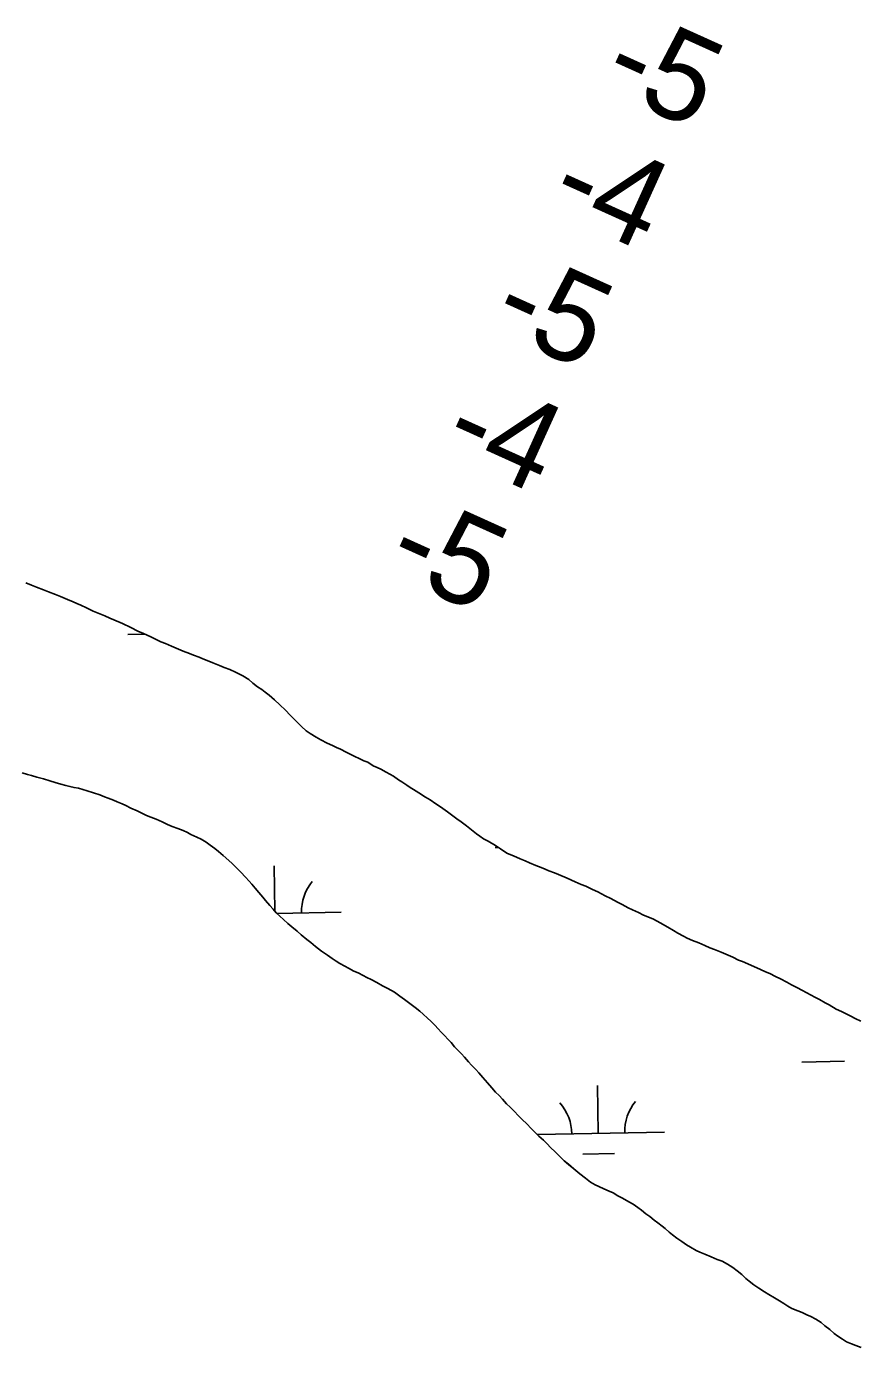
# Model space of a CAD drawing. Extents: x 3989314 to 4027622, y 243956 to 270014.
# Drawn here: x 4017755 to 4018382, y 254007 to 255004 of the extents above; entities that cross this region are included whole.
import ezdxf

# ---------------------------------------------------------------- set-up
doc = ezdxf.new("R2010")
doc.units = 0
for name, color, linetype in [('V-RIVR-EDGE', 7, 'Continuous'), ('V-RIVR-RANG', 7, 'Continuous'), ('V-WETL-SWMP', 7, 'Continuous')]:
    doc.layers.add(name, color=color, linetype=linetype)

msp = doc.modelspace()

# ---------------------------------------------------------------- linework, layer by layer
at = {"layer": 'V-RIVR-EDGE'}
for points in [[(4017754.1, 254584.42), (4017758.41, 254582.49), (4017762.19, 254580.94), (4017767.4, 254579.01), (4017771.32, 254577.47), (4017776.53, 254575.54), (4017780.45, 254574.13), (4017785.66, 254571.68), (4017789.84, 254569.87), (4017792.7, 254568.71), (4017795.71, 254567.56), (4017799.88, 254565.49), (4017805.1, 254563.04), (4017808.88, 254561.5), (4017813.83, 254559.31), (4017817.62, 254557.77), (4017820.49, 254556.48), (4017827.01, 254553.52), (4017833.4, 254550.55), (4017838.75, 254547.97), (4017842.93, 254546.04), (4017848.41, 254543.46), (4017852.97, 254541.27), (4017856.1, 254539.85), (4017859.49, 254538.43), (4017864.06, 254536.63), (4017869.27, 254534.31), (4017872.93, 254532.77), (4017877.62, 254531.1), (4017880.75, 254529.81), (4017884.92, 254528.27), (4017887.79, 254526.98), (4017892.1, 254525.31), (4017895.23, 254523.89), (4017900.18, 254521.83), (4017903.7, 254520.54), (4017908.01, 254518.87), (4017912.44, 254516.81), (4017917.79, 254514.23), (4017922.49, 254511.26), (4017925.5, 254508.54), (4017929.02, 254505.82), (4017932.16, 254503.75), (4017934.64, 254501.94)], [(4017934.64, 254501.94), (4017937.77, 254499.48), (4017941.69, 254496.12), (4017945.88, 254492.36), (4017950.06, 254488.21), (4017953.59, 254484.58), (4017956.08, 254481.99), (4017959.61, 254478.49), (4017962.09, 254475.9), (4017965.75, 254472.67), (4017968.76, 254470.6), (4017973.2, 254467.75), (4017976.59, 254465.95), (4017981.55, 254463.37), (4017985.46, 254461.56), (4017988.46, 254460.14), (4017991.46, 254458.73), (4017995.77, 254456.53), (4017998.77, 254454.98), (4018001.77, 254453.57), (4018006.21, 254451.5), (4018009.08, 254450.08), (4018012.08, 254448.93), (4018016.12, 254446.34), (4018019.12, 254445.05), (4018021.86, 254443.64), (4018025.91, 254441.44), (4018028.78, 254439.89), (4018031.39, 254438.34), (4018035.18, 254435.76), (4018037.79, 254434.08), (4018041.57, 254431.62), (4018044.06, 254429.81), (4018046.67, 254428.26), (4018050.58, 254425.93), (4018055.67, 254422.71), (4018059.07, 254420.51), (4018063.38, 254417.66), (4018066.9, 254415.34), (4018072.12, 254411.58), (4018076.17, 254408.61), (4018079.31, 254406.28), (4018082.45, 254403.95), (4018086.49, 254400.98), (4018088.98, 254398.9), (4018094.07, 254395.02), (4018096.55, 254393.08), (4018099.3, 254391.14), (4018102.95, 254389.34), (4018108.43, 254386.11), (4018112.22, 254383.52), (4018114.83, 254381.84), (4018117.57, 254380.16), (4018122.14, 254378.23), (4018127.09, 254376.17), (4018130.74, 254374.5), (4018134.13, 254373.08), (4018138.96, 254371.15), (4018143, 254369.48), (4018145.87, 254368.32), (4018148.74, 254367.03), (4018153.05, 254365.49), (4018155.92, 254364.2), (4018162.44, 254361.36), (4018168.56, 254358.79), (4018173.13, 254356.73), (4018176.65, 254355.44), (4018181.61, 254352.99), (4018185.66, 254351.06), (4018188.39, 254349.77), (4018191.27, 254348.22), (4018195.44, 254346.03), (4018200.53, 254343.45), (4018204.05, 254341.51), (4018208.62, 254339.19), (4018211.88, 254337.64), (4018216.32, 254335.45), (4018220.1, 254333.51), (4018224.66, 254331.71), (4018227.53, 254330.55), (4018232.75, 254327.71), (4018238.37, 254324.49), (4018242.67, 254321.9), (4018245.94, 254319.96), (4018250.11, 254317.64), (4018253.11, 254316.22), (4018257.03, 254314.55), (4018261.72, 254312.62), (4018266.29, 254310.55), (4018270.2, 254308.88), (4018273.72, 254307.6), (4018278.54, 254305.54), (4018282.07, 254304.12), (4018287.42, 254301.8), (4018291.72, 254299.61), (4018294.72, 254298.58), (4018298.76, 254296.91), (4018301.63, 254295.62), (4018305.42, 254293.81), (4018308.28, 254292.65), (4018312.2, 254290.85)], [(4018051.47, 254261.01), (4018047.81, 254263.99), (4018044.81, 254266.19), (4018039.85, 254269.94), (4018036.32, 254272.4), (4018032.14, 254275.37), (4018027.31, 254278.21), (4018023.27, 254280.28), (4018018.96, 254282.73), (4018014.78, 254284.92), (4018011.39, 254286.6), (4018008.65, 254288.02), (4018004.74, 254290.08), (4018001.61, 254291.37), (4017997.69, 254293.57), (4017994.82, 254295.11), (4017991.04, 254297.18), (4017988.29, 254298.73), (4017985.16, 254300.8), (4017981.64, 254303.26), (4017977.19, 254306.49), (4017972.75, 254309.85), (4017969.09, 254312.96), (4017966.22, 254315.29), (4017961.91, 254318.79), (4017958.77, 254321.37), (4017954.72, 254324.87), (4017951.85, 254327.33), (4017948.58, 254330.31), (4017945.83, 254332.77), (4017943.09, 254335.36), (4017940.73, 254338.08), (4017938.25, 254340.93), (4017934.97, 254344.7), (4017932.88, 254347.16), (4017930, 254350.66), (4017927.12, 254354.03), (4017924.63, 254356.88), (4017922.67, 254359.22), (4017919.79, 254362.2), (4017916.26, 254365.96), (4017912.73, 254369.59), (4017909.85, 254372.44), (4017907.37, 254374.77), (4017903.06, 254378.65), (4017899.53, 254381.63), (4017896.78, 254383.83), (4017893.26, 254386.42), (4017890.12, 254388.62), (4017886.34, 254390.81), (4017883.07, 254392.49), (4017878.77, 254394.42), (4017876.03, 254395.97), (4017872.77, 254397.39), (4017868.73, 254398.93), (4017864.68, 254400.48), (4017861.16, 254402.02), (4017857.12, 254403.96), (4017852.42, 254406.02), (4017848.51, 254407.43), (4017845.25, 254408.85), (4017841.21, 254410.78), (4017838.21, 254412.2), (4017833.38, 254414.39), (4017829.73, 254416.19), (4017826.86, 254417.49), (4017823.2, 254419.16), (4017820.33, 254420.32), (4017816.42, 254421.86), (4017813.56, 254422.89), (4017809.9, 254424.3), (4017805.34, 254425.85), (4017800.39, 254427.39), (4017797.13, 254428.28), (4017794, 254429.31), (4017790.61, 254429.81), (4017787.48, 254430.71), (4017784.36, 254431.48), (4017780.58, 254432.5), (4017776.27, 254433.78), (4017772.36, 254434.94), (4017767.41, 254436.35), (4017762.46, 254437.75), (4017758.55, 254438.91), (4017755.42, 254439.8), (4017751.38, 254440.96)], [(4018312.2, 254290.85), (4018315.33, 254289.43), (4018319.63, 254287.24), (4018323.42, 254285.44), (4018328.25, 254282.98), (4018331.77, 254281.05), (4018336.34, 254278.6), (4018339.47, 254276.92), (4018343.38, 254274.98), (4018345.99, 254273.43), (4018349.91, 254271.5), (4018352.78, 254269.95), (4018356.96, 254267.49), (4018360.22, 254265.82), (4018365.44, 254262.72), (4018369.35, 254260.78), (4018372.35, 254259.24), (4018376.53, 254257.3), (4018379.66, 254255.62), (4018383.96, 254253.69)], [(4018377.02, 254010.11), (4018373.23, 254011.65), (4018370.1, 254013.72), (4018366.57, 254015.92), (4018363.83, 254017.99), (4018360.56, 254020.84), (4018356.91, 254023.81), (4018354.03, 254026.27), (4018350.12, 254028.73), (4018346.2, 254030.66), (4018343.33, 254031.95), (4018339.81, 254033.63), (4018336.55, 254035.05), (4018331.85, 254036.85), (4018328.98, 254038.52), (4018325.98, 254040.46), (4018322.71, 254042.53), (4018318.93, 254044.86), (4018314.62, 254047.44), (4018311.36, 254049.38), (4018307.05, 254052.09), (4018303.39, 254054.55), (4018299.74, 254057.4), (4018297.25, 254059.47), (4018294.12, 254062.32), (4018290.59, 254065.16), (4018287.32, 254067.75), (4018283.54, 254070.21), (4018279.36, 254072.53), (4018275.71, 254073.82), (4018271.14, 254075.75), (4018266.32, 254077.68), (4018262.54, 254079.22), (4018259.8, 254080.64), (4018255.62, 254082.97), (4018252.62, 254084.91), (4018248.96, 254087.23), (4018245.3, 254089.82), (4018242.04, 254092.28), (4018239.43, 254094.35), (4018236.42, 254097.07), (4018234.07, 254099.01), (4018230.8, 254101.47), (4018228.19, 254103.54), (4018224.79, 254106.12), (4018221.92, 254108.19), (4018218.52, 254110.91), (4018215.91, 254112.85), (4018212.25, 254115.44), (4018208.99, 254117.25), (4018204.29, 254120.09), (4018200.77, 254121.9), (4018197.25, 254123.96), (4018194.25, 254125.25), (4018190.07, 254127.18), (4018186.42, 254128.73), (4018183.68, 254130.15), (4018180.15, 254132.21), (4018176.23, 254135.19), (4018172.06, 254138.42), (4018167.61, 254142.05), (4018163.43, 254145.55), (4018160.29, 254148.26), (4018156.24, 254152.15), (4018153.37, 254154.87), (4018149.83, 254158.37), (4018147.35, 254160.96), (4018144.6, 254163.68), (4018141.07, 254166.92), (4018137.93, 254170.16), (4018135.45, 254172.62), (4018132.05, 254175.99), (4018128.52, 254179.49), (4018125.38, 254182.6), (4018123.02, 254185.19), (4018119.5, 254188.69), (4018116.75, 254191.28), (4018113.61, 254194.78), (4018111.12, 254197.5), (4018108.51, 254200.09), (4018105.76, 254203.2), (4018102.49, 254206.96), (4018098.96, 254210.99), (4018095.95, 254214.49), (4018093.59, 254217.08), (4018090.45, 254220.45), (4018088.1, 254222.91), (4018085.09, 254226.41), (4018082.73, 254228.87), (4018079.85, 254231.99), (4018077.63, 254234.32), (4018074.88, 254237.43), (4018072.79, 254239.63), (4018070.04, 254242.74), (4018067.82, 254245.08), (4018064.94, 254247.93), (4018062.85, 254250.26), (4018059.58, 254253.5), (4018057.22, 254255.83), (4018053.96, 254258.81), (4018051.47, 254261.01)], [(4018384.32, 254007.28), (4018380.15, 254008.82), (4018377.02, 254010.11)]]:
    msp.add_lwpolyline(points, dxfattribs=at)
at = {"layer": 'V-WETL-SWMP'}
for p, q in [((4017831.11, 254545.33), (4017843.88, 254545.59)), ((4018108.27, 254384.65), (4018110.5, 254384.7)), ((4017942.13, 254336.46), (4017941.45, 254370.89)), ((4017943.54, 254334.93), (4017992.16, 254335.9)), ((4018339.54, 254222.73), (4018371.54, 254223.36)), ((4018185.99, 254168.91), (4018185.28, 254204.91)), ((4018140.03, 254168), (4018235.98, 254169.91)), ((4018174.3, 254153.25), (4018198.3, 254153.73))]:
    msp.add_line(p, q, dxfattribs=at)
for points in [[(4017754.1, 254584.42), (4017758.41, 254582.49), (4017762.19, 254580.94), (4017767.4, 254579.01), (4017771.32, 254577.47), (4017776.53, 254575.54), (4017780.44, 254574.13), (4017785.66, 254571.68), (4017789.84, 254569.87), (4017792.71, 254568.72), (4017795.7, 254567.56), (4017799.88, 254565.49), (4017805.1, 254563.05), (4017808.88, 254561.5), (4017813.84, 254559.31), (4017817.62, 254557.77), (4017820.49, 254556.48), (4017827.01, 254553.51), (4017833.4, 254550.55), (4017838.75, 254547.97), (4017842.93, 254546.04), (4017848.41, 254543.46), (4017852.97, 254541.27), (4017856.1, 254539.85), (4017859.49, 254538.43), (4017864.06, 254536.63), (4017869.27, 254534.31), (4017872.93, 254532.77), (4017877.62, 254531.1), (4017880.75, 254529.81), (4017884.92, 254528.27), (4017887.79, 254526.98), (4017892.1, 254525.31), (4017895.23, 254523.89), (4017900.18, 254521.83), (4017903.7, 254520.54), (4017908.01, 254518.87), (4017912.44, 254516.81), (4017917.79, 254514.23), (4017922.49, 254511.26), (4017925.5, 254508.54), (4017929.02, 254505.82), (4017932.16, 254503.75), (4017934.64, 254501.94), (4017937.77, 254499.48), (4017941.7, 254496.12), (4017945.88, 254492.36), (4017950.06, 254488.21), (4017953.59, 254484.58), (4017956.08, 254481.99), (4017959.61, 254478.49), (4017962.1, 254475.9), (4017965.75, 254472.67), (4017968.76, 254470.6), (4017973.2, 254467.75), (4017976.59, 254465.95), (4017981.55, 254463.37), (4017985.46, 254461.56), (4017988.46, 254460.14), (4017991.46, 254458.73), (4017995.77, 254456.53), (4017998.77, 254454.98), (4018001.77, 254453.57), (4018006.21, 254451.5), (4018009.08, 254450.08)], [(4018009.08, 254450.08), (4018012.08, 254448.93), (4018016.12, 254446.34), (4018019.12, 254445.05), (4018021.86, 254443.64), (4018025.91, 254441.44), (4018028.78, 254439.89), (4018031.39, 254438.34), (4018035.18, 254435.76), (4018037.79, 254434.08), (4018041.57, 254431.62), (4018044.06, 254429.81), (4018046.67, 254428.26), (4018050.58, 254425.93), (4018055.67, 254422.7), (4018059.07, 254420.51), (4018063.38, 254417.66), (4018066.9, 254415.34), (4018072.13, 254411.58), (4018076.18, 254408.61), (4018079.31, 254406.28), (4018082.45, 254403.95), (4018086.49, 254400.98), (4018088.98, 254398.91), (4018094.07, 254395.02), (4018096.55, 254393.08), (4018099.3, 254391.14), (4018102.95, 254389.34), (4018108.43, 254386.11), (4018112.22, 254383.52), (4018114.83, 254381.84), (4018117.57, 254380.16), (4018122.14, 254378.23), (4018127.09, 254376.17), (4018130.74, 254374.5), (4018134.14, 254373.08), (4018138.96, 254371.15), (4018143, 254369.48), (4018145.87, 254368.32), (4018148.74, 254367.03), (4018153.04, 254365.49), (4018155.92, 254364.2), (4018162.44, 254361.36), (4018168.57, 254358.79), (4018173.13, 254356.73), (4018176.65, 254355.44), (4018181.61, 254352.99), (4018185.66, 254351.06), (4018188.39, 254349.77), (4018191.27, 254348.22), (4018195.44, 254346.03), (4018200.53, 254343.45), (4018204.05, 254341.51), (4018208.62, 254339.19), (4018211.88, 254337.64), (4018216.32, 254335.45), (4018220.1, 254333.51), (4018224.67, 254331.71), (4018227.53, 254330.55), (4018232.75, 254327.71), (4018238.37, 254324.49), (4018242.67, 254321.9), (4018245.94, 254319.96), (4018250.11, 254317.64), (4018253.11, 254316.22), (4018257.03, 254314.55), (4018261.72, 254312.62), (4018266.29, 254310.55), (4018270.2, 254308.88), (4018273.72, 254307.6), (4018278.55, 254305.54), (4018282.07, 254304.12), (4018287.42, 254301.8), (4018291.72, 254299.61), (4018294.72, 254298.58), (4018298.76, 254296.91), (4018301.63, 254295.62), (4018305.42, 254293.81), (4018308.29, 254292.65), (4018312.2, 254290.85), (4018315.33, 254289.43), (4018319.64, 254287.24), (4018323.42, 254285.43), (4018328.25, 254282.98), (4018331.77, 254281.05), (4018336.34, 254278.6), (4018339.47, 254276.92), (4018343.38, 254274.98), (4018345.99, 254273.43), (4018349.91, 254271.5), (4018352.78, 254269.95), (4018356.96, 254267.5), (4018360.22, 254265.82), (4018365.44, 254262.72), (4018369.35, 254260.78), (4018372.35, 254259.24), (4018376.53, 254257.3), (4018379.66, 254255.62), (4018383.96, 254253.69)], [(4017784.36, 254431.48), (4017780.58, 254432.5), (4017776.27, 254433.78), (4017772.36, 254434.94), (4017767.41, 254436.35), (4017762.46, 254437.75), (4017758.55, 254438.91), (4017755.42, 254439.8), (4017751.38, 254440.96)], [(4018113.61, 254194.78), (4018111.12, 254197.5), (4018108.51, 254200.09), (4018105.76, 254203.21), (4018102.49, 254206.96), (4018098.96, 254210.98), (4018095.95, 254214.49), (4018093.59, 254217.08), (4018090.45, 254220.45), (4018088.1, 254222.91), (4018085.09, 254226.41), (4018082.73, 254228.87), (4018079.85, 254231.98), (4018077.63, 254234.32), (4018074.88, 254237.43), (4018072.79, 254239.63), (4018070.04, 254242.74), (4018067.82, 254245.08), (4018064.94, 254247.93), (4018062.85, 254250.26), (4018059.58, 254253.5), (4018057.22, 254255.83), (4018053.96, 254258.81), (4018051.47, 254261.01), (4018047.81, 254263.99), (4018044.81, 254266.19), (4018039.85, 254269.94), (4018036.32, 254272.4), (4018032.14, 254275.37), (4018027.31, 254278.21), (4018023.27, 254280.28), (4018018.96, 254282.73), (4018014.78, 254284.92), (4018011.39, 254286.6), (4018008.65, 254288.02), (4018004.74, 254290.08), (4018001.61, 254291.37), (4017997.69, 254293.57), (4017994.82, 254295.12), (4017991.04, 254297.18), (4017988.29, 254298.73), (4017985.16, 254300.8), (4017981.64, 254303.26), (4017977.2, 254306.49), (4017972.75, 254309.85), (4017969.1, 254312.96), (4017966.22, 254315.29), (4017961.91, 254318.79), (4017958.77, 254321.37), (4017954.72, 254324.87), (4017951.85, 254327.33), (4017948.58, 254330.31), (4017945.83, 254332.77), (4017943.09, 254335.36), (4017940.73, 254338.08), (4017938.25, 254340.93), (4017934.97, 254344.7), (4017932.88, 254347.16), (4017930, 254350.66), (4017927.12, 254354.03), (4017924.63, 254356.88), (4017922.67, 254359.22), (4017919.79, 254362.2), (4017916.26, 254365.96), (4017912.73, 254369.59), (4017909.85, 254372.44), (4017907.37, 254374.77), (4017903.06, 254378.65), (4017899.53, 254381.63), (4017896.78, 254383.83), (4017893.26, 254386.42), (4017890.12, 254388.62), (4017886.34, 254390.81), (4017883.08, 254392.49), (4017878.77, 254394.42), (4017876.03, 254395.97), (4017872.77, 254397.39), (4017868.73, 254398.93), (4017864.68, 254400.48), (4017861.16, 254402.02), (4017857.12, 254403.96), (4017852.42, 254406.02), (4017848.51, 254407.43), (4017845.25, 254408.85), (4017841.21, 254410.78), (4017838.21, 254412.2), (4017833.38, 254414.39), (4017829.73, 254416.2), (4017826.86, 254417.48), (4017823.2, 254419.16), (4017820.33, 254420.32), (4017816.42, 254421.86), (4017813.55, 254422.89), (4017809.9, 254424.3), (4017805.34, 254425.85), (4017800.39, 254427.39), (4017797.13, 254428.28), (4017794, 254429.31), (4017790.61, 254429.81), (4017787.48, 254430.71), (4017784.36, 254431.48)], [(4018384.32, 254007.28), (4018380.15, 254008.82), (4018377.02, 254010.11), (4018373.23, 254011.65), (4018370.1, 254013.72), (4018366.58, 254015.92), (4018363.83, 254017.99), (4018360.56, 254020.84), (4018356.91, 254023.81), (4018354.03, 254026.27), (4018350.12, 254028.73), (4018346.2, 254030.66), (4018343.33, 254031.95), (4018339.81, 254033.63), (4018336.55, 254035.05), (4018331.85, 254036.85), (4018328.98, 254038.52), (4018325.98, 254040.46), (4018322.71, 254042.53), (4018318.93, 254044.86), (4018314.62, 254047.44), (4018311.36, 254049.38), (4018307.05, 254052.09), (4018303.39, 254054.55), (4018299.74, 254057.4), (4018297.25, 254059.47), (4018294.12, 254062.32), (4018290.59, 254065.16), (4018287.32, 254067.75), (4018283.54, 254070.21), (4018279.36, 254072.53), (4018275.71, 254073.82), (4018271.14, 254075.75), (4018266.32, 254077.68), (4018262.54, 254079.22), (4018259.8, 254080.64), (4018255.62, 254082.97), (4018252.62, 254084.9), (4018248.96, 254087.23), (4018245.31, 254089.82), (4018242.04, 254092.28), (4018239.43, 254094.35), (4018236.42, 254097.07), (4018234.07, 254099.01), (4018230.8, 254101.47), (4018228.19, 254103.54), (4018224.79, 254106.12), (4018221.92, 254108.19), (4018218.52, 254110.91), (4018215.91, 254112.85), (4018212.25, 254115.44), (4018208.99, 254117.25), (4018204.29, 254120.09), (4018200.77, 254121.9), (4018197.25, 254123.96), (4018194.25, 254125.25), (4018190.07, 254127.18), (4018186.42, 254128.73), (4018183.68, 254130.15), (4018180.15, 254132.21), (4018176.24, 254135.19), (4018172.06, 254138.43), (4018167.61, 254142.05), (4018163.43, 254145.54), (4018160.29, 254148.26), (4018156.24, 254152.15), (4018153.37, 254154.87), (4018149.83, 254158.37), (4018147.35, 254160.96), (4018144.6, 254163.68), (4018141.07, 254166.92), (4018137.93, 254170.16), (4018135.45, 254172.62), (4018132.05, 254175.99), (4018128.52, 254179.49), (4018125.38, 254182.6), (4018123.02, 254185.19), (4018119.5, 254188.69), (4018116.75, 254191.28), (4018113.61, 254194.78)]]:
    msp.add_lwpolyline(points, dxfattribs=at)
for centre, start, end in [((4017997.39, 254336.48), 140.36987, 181.91353), ((4018130.75, 254168.29), 0.36988, 41.91354), ((4018241.22, 254170.49), 140.36987, 181.91353)]:
    msp.add_arc(centre, 35.25, start, end, dxfattribs=at)

# ---------------------------------------------------------------- texts
at = {"layer": 'V-RIVR-RANG'}
for s, p in [('-5', (4018186.18, 254958.47)), ('-4', (4018146.25, 254867.11)), ('-5', (4018102.93, 254776.79)), ('-4', (4018065.87, 254683.72)), ('-5', (4018023.42, 254593.46))]:
    msp.add_text(s, height=67, rotation=335.67144, dxfattribs=at).set_placement(p)

doc.saveas('drawing.dxf')
